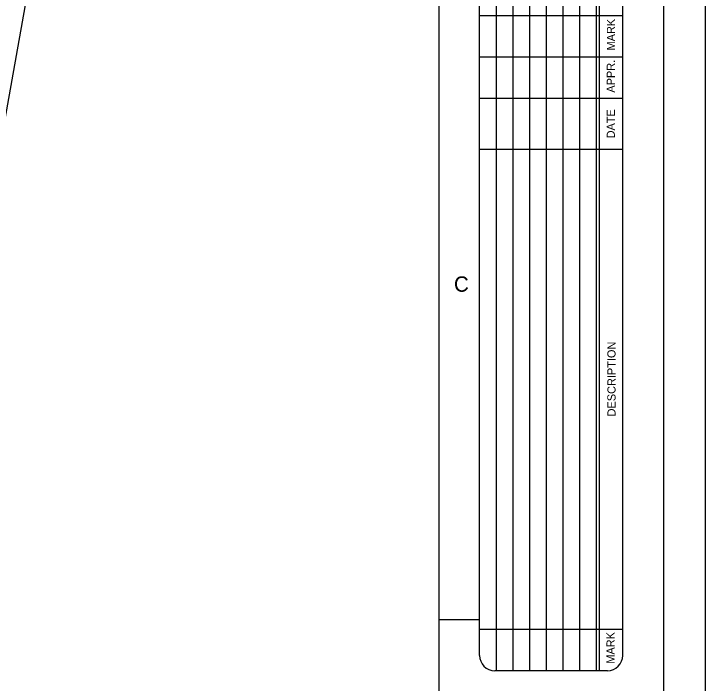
# Model space of a CAD drawing. Extents: x 22369.6 to 22428.3, y 22369.6 to 22415.
# Drawn here: x 22417.01 to 22428.29, y 22391.26 to 22402.17 of the extents above; entities that cross this region are included whole.
import ezdxf

# ---------------------------------------------------------------- set-up
doc = ezdxf.new("R2010")
doc.units = 0
for name, color, linetype in [('Level 1', 7, 'Continuous'), ('Level 10', 7, 'Continuous'), ('Level 7', 7, 'Continuous'), ('Level 9', 7, 'Continuous')]:
    doc.layers.add(name, color=color, linetype=linetype)

msp = doc.modelspace()

# ---------------------------------------------------------------- linework, layer by layer
at = {"layer": 'Level 1'}
for p, q in [((22424.88, 22411.461), (22424.88, 22391.461)), ((22425.152, 22411.461), (22425.152, 22391.461)), ((22425.424, 22411.461), (22425.424, 22391.461)), ((22425.696, 22411.461), (22425.696, 22391.461)), ((22425.968, 22411.461), (22425.968, 22391.461)), ((22426.24, 22411.461), (22426.24, 22391.461)), ((22426.512, 22411.461), (22426.512, 22391.461)), ((22426.56, 22411.461), (22426.56, 22391.461)), ((22416.028, 22395.738), (22417.23, 22402.453)), ((22426.944, 22401.461), (22424.608, 22401.461)), ((22426.694, 22391.461), (22424.858, 22391.461))]:
    msp.add_line(p, q, dxfattribs=at)
msp.add_lwpolyline([(22369.621, 22414.965), (22428.288, 22414.965), (22428.288, 22369.621), (22369.621, 22369.621)], close=True, dxfattribs=at)
for points in [[(22424.608, 22391.711), (22424.608, 22411.211)], [(22426.944, 22391.711), (22426.944, 22411.211)]]:
    msp.add_lwpolyline(points, dxfattribs=at)
for centre, start, end in [((22424.858, 22391.711), 180, 270), ((22426.694, 22391.711), 270, 0)]:
    msp.add_arc(centre, 0.25, start, end, dxfattribs=at)
at = {"layer": 'Level 10'}
msp.add_line((22423.952, 22392.293), (22424.608, 22392.293), dxfattribs=at)
at = {"layer": 'Level 7'}
for p, q in [((22426.944, 22400.789), (22424.608, 22400.789)), ((22426.944, 22399.956), (22424.608, 22399.956)), ((22426.944, 22392.133), (22424.608, 22392.133))]:
    msp.add_line(p, q, dxfattribs=at)
msp.add_lwpolyline([(22426.944, 22402.133), (22424.608, 22402.133)], dxfattribs=at)
at = {"layer": 'Level 9'}
msp.add_line((22427.616, 22370.293), (22427.616, 22414.293), dxfattribs=at)
msp.add_lwpolyline([(22423.952, 22370.293), (22423.952, 22414.293)], dxfattribs=at)

# ---------------------------------------------------------------- texts
at = {"layer": 'Level 1'}
for s, height, p in [('MARK', 0.1333, (22426.819, 22401.57)), ('APPR.', 0.1333, (22426.816, 22400.882)), ('DATE', 0.1333, (22426.816, 22400.137)), ('DESCRIPTION', 0.13333, (22426.827, 22395.605)), ('MARK', 0.1333, (22426.812, 22391.575))]:
    msp.add_text(s, height=height, rotation=90, dxfattribs=at).set_placement(p)
msp.add_text('C', height=0.25, dxfattribs=at).set_placement((22424.192, 22397.637))

doc.saveas('drawing.dxf')
